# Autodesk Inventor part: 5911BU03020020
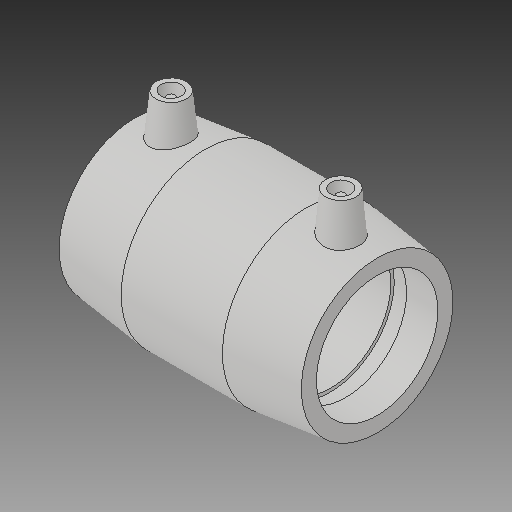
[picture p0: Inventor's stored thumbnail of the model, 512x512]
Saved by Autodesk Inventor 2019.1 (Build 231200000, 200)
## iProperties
Created: 2017-06
Part Number: 5911BU03020020
Material: Generic
Description: PLASSON ASTM REDUCING COUPLER 2''IPS-2''CTS
Document SubType Name: Modeling
Designer: KIM
Mass: 54.8237 g
Surface Area: 155.252 cm^2
Volume: 54.8237 cm^3
Density: 1 g/cm^3
Appearance: Default
Author: KIM
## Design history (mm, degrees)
derived "5911.ipt"
feature "Solid1::5911.ipt"
tag "TaggingFeature1"
body "Solid1"
other parameters: "d0" = 119.888, "d2" = 83.312, "d3" = 58.166, "d4" = 34.8996, "d5" = 74.9808, "d7" = 53.8, "d8" = 168 deg, "d10" = 23.2664, "d11" = 7.75547, "d14" = 17.6296, "d22" = 108.92847, "d29" = 58.42, "d30" = 15, "d31" = 41.9608, "d34" = 6 deg, "d41" = 4, "d42" = 14, "d43" = 0, "d48" = 83.312, "d49" = 60.1, "d50" = 83.312, "d52" = 48.42, "d53" = 23.2664, "d54" = 7.75547, "d55" = 168 deg, "d56" = 34.8996, "d57" = 58.166, "d58" = 74.9808, "d59" = 2.9083, "d60" = 135 deg, "d61" = 58.42, "d62" = 15, "d64" = 4, "d66" = 5 deg, "d67" = 14, "d68" = 0, "d69" = 41.9608, "d95" = 3, "d96" = 0, "d97" = 3, "d98" = 0, "d_1" = 53.8, "L_" = 119.888, "L_2" = 58.166, "D_1" = 83.312, "A_1" = 58.42, "d_2" = 12, "L_1" = 58.166, "d_" = 60.1, "A_" = 58.42, "D_" = 83.312
